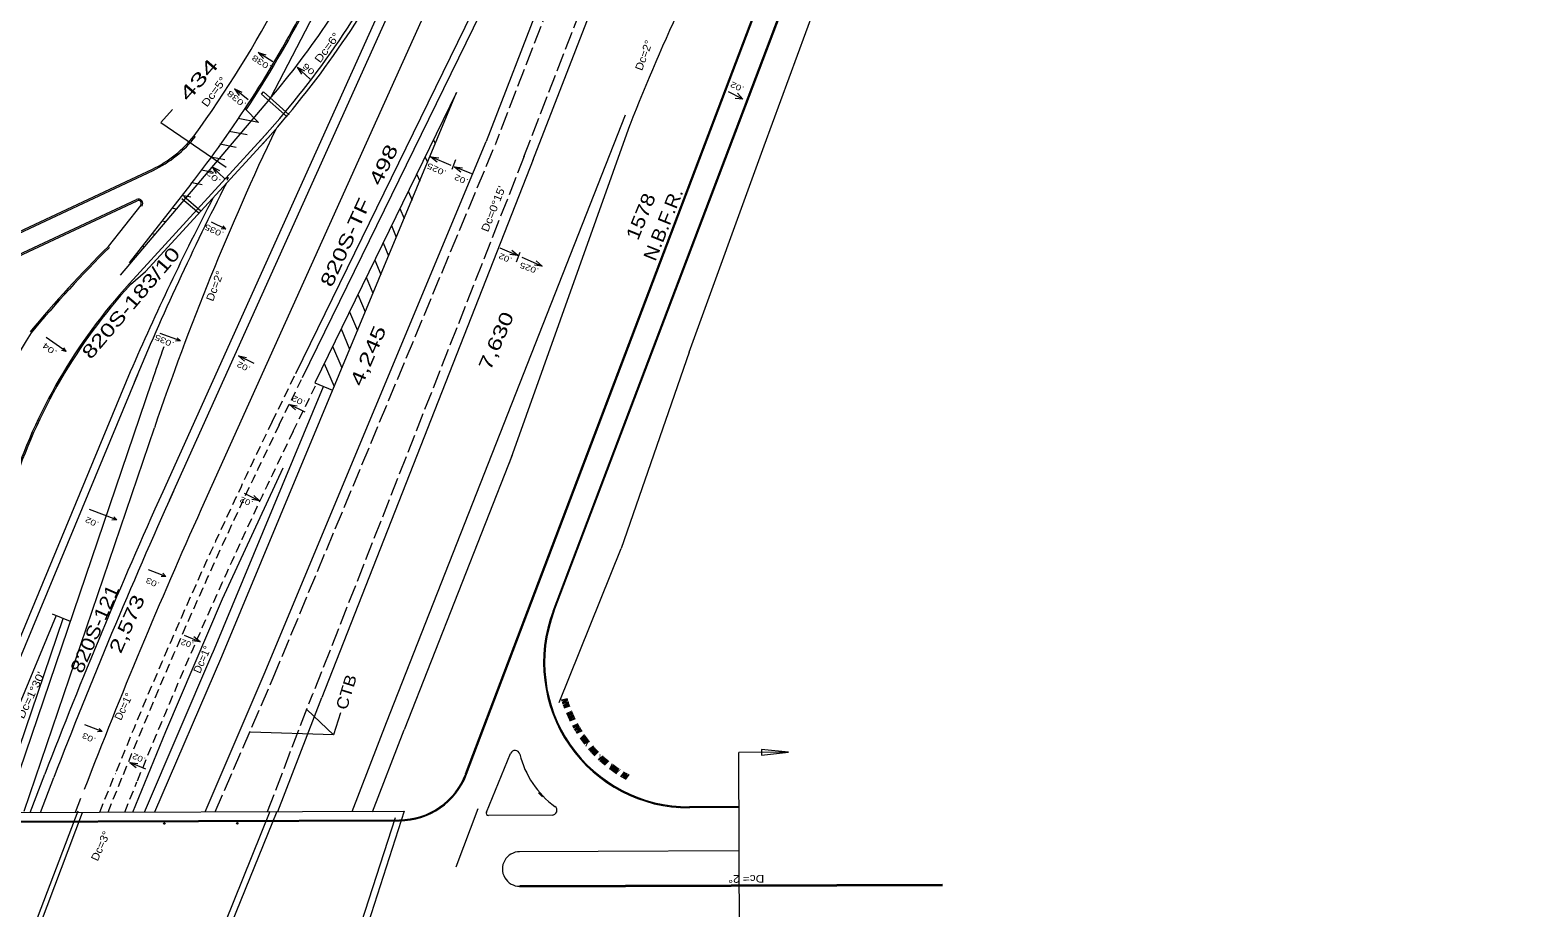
# Model space of a CAD drawing. Extents: x 2354993 to 2372084, y 6966390 to 6990057.
# Drawn here: x 2364884 to 2366452, y 6980481 to 6981393 of the extents above; entities that cross this region are included whole.
import ezdxf

# ---------------------------------------------------------------- set-up
doc = ezdxf.new("R2010")
doc.units = 0
doc.header["$LTSCALE"] = 3.2
doc.header["$PDMODE"] = 32
doc.header["$PDSIZE"] = 1.6
doc.linetypes.add('LONG_DASHED', pattern=[7.5, 6, -1.5])
doc.linetypes.add('MEDIUM_DASHED', pattern=[4.5, 3, -1.5])
for name, color, linetype, lineweight in [('1', 7, 'Continuous', 35), ('11', 7, 'Continuous', 13), ('12', 7, 'Continuous', 13), ('13', 7, 'Continuous', 13), ('15', 7, 'Continuous', 13), ('17', 7, 'Continuous', 13), ('19', 7, 'Continuous', 13), ('25', 7, 'Continuous', 13), ('4', 7, 'Continuous', 13), ('5', 7, 'Continuous', 13), ('7', 7, 'Continuous', 13), ('9', 7, 'Continuous', 13)]:
    doc.layers.add(name, color=color, linetype=linetype, lineweight=lineweight)

msp = doc.modelspace()

# ---------------------------------------------------------------- linework, layer by layer
at = {"layer": '1'}
msp.add_line((2365393.484, 6980503.184), (2365832.993, 6980504.618), dxfattribs=at)
at = {"layer": '11'}
for q in [(2365610.405, 6981329.056), (2365619.803, 6981327.948), (2365617.401, 6981322.432)]:
    msp.add_line((2365625.59, 6981321.562), q, dxfattribs=at)
msp.add_lwpolyline([(2365417.107, 6980596.157), (2365413.024, 6980600.471), (2365417.107, 6980596.157)], dxfattribs=at)
at = {"layer": '12'}
for p, q in [((2365125.058, 6981326.907), (2365127.058, 6981329.143)), ((2365125.058, 6981326.907), (2365151.575, 6981303.182)), ((2365127.058, 6981329.143), (2365153.598, 6981305.398)), ((2365059.879, 6981202.904), (2365042.143, 6981217.955)), ((2365061.904, 6981205.119), (2365044.105, 6981220.225)), ((2364889.34, 6980463.063), (2364934.323, 6980581.712)), ((2364895.069, 6980464.071), (2364938.998, 6980579.939)), ((2365133.691, 6980580.838), (2365086.673, 6980464.691)), ((2365140.767, 6980580.861), (2365093.748, 6980464.714)), ((2365263.831, 6980574.448), (2365228.608, 6980465.09)), ((2365273.39, 6980581.292), (2365235.902, 6980464.902))]:
    msp.add_line(p, q, dxfattribs=at)
at = {"layer": '13'}
msp.add_lwpolyline([(2365032.472, 6981310.938), (2365020.251, 6981297.462), (2365088.313, 6981250.891)], dxfattribs=at)
at = {"layer": '15'}
for p in [(2365672.832, 6980642.571), (2365622.178, 6980409.332)]:
    msp.add_line(p, (2365621.422, 6980642.404), dxfattribs=at)
msp.add_lwpolyline([(2365672.832, 6980642.571), (2365644.822, 6980645.48), (2365644.842, 6980639.481)], close=True, dxfattribs=at)
at = {"layer": '19'}
for p, q in [((2365121.444, 6981370.154), (2365126.945, 6981363.93)), ((2365121.444, 6981370.154), (2365129.403, 6981367.761)), ((2365136.609, 6981360.443), (2365121.444, 6981370.154)), ((2365162.209, 6981354.708), (2365166.546, 6981347.624)), ((2365162.209, 6981354.708), (2365169.632, 6981350.969)), ((2365175.457, 6981342.512), (2365162.209, 6981354.708)), ((2365097.007, 6981332.243), (2365101.772, 6981325.439)), ((2365097.007, 6981332.243), (2365104.646, 6981328.969)), ((2365110.982, 6981320.886), (2365097.007, 6981332.243)), ((2365301.151, 6981261.455), (2365307.649, 6981256.281)), ((2365301.151, 6981261.455), (2365309.405, 6981260.48)), ((2365322.242, 6981252.661), (2365301.151, 6981261.455)), ((2365073.768, 6981251.325), (2365077.965, 6981244.157)), ((2365073.768, 6981251.325), (2365081.116, 6981247.442)), ((2365086.775, 6981238.871), (2365073.768, 6981251.325)), ((2365326.815, 6981258.432), (2365322.862, 6981248.333)), ((2365325.805, 6981251.294), (2365332.303, 6981246.12)), ((2365325.805, 6981251.294), (2365334.058, 6981250.319)), ((2365343.62, 6981243.866), (2365325.805, 6981251.294)), ((2365101.134, 6981054.568), (2365107.331, 6981049.037)), ((2365101.134, 6981054.568), (2365109.32, 6981053.131)), ((2365117.339, 6981046.715), (2365101.134, 6981054.568)), ((2365153.99, 6981004.019), (2365160.187, 6980998.488)), ((2365153.99, 6981004.019), (2365162.176, 6981002.582)), ((2365170.195, 6980996.166), (2365153.99, 6981004.019)), ((2365122.978, 6980903.802), (2365114.831, 6980905.444)), ((2365061.108, 6980757.5), (2365052.846, 6980758.396)), ((2364988.033, 6980631.938), (2364996.28, 6980630.907))]:
    msp.add_line(p, q, dxfattribs=at)
for points in [[(2365106.977, 6980912.062), (2365122.978, 6980903.802), (2365116.923, 6980909.487)], [(2365044.423, 6980764.273), (2365061.108, 6980757.5), (2365054.562, 6980762.612)], [(2365004.606, 6980624.894), (2364988.033, 6980631.938), (2364994.495, 6980626.72)]]:
    msp.add_lwpolyline(points, dxfattribs=at)
at = {"layer": '25'}
for p, q in [((2365683.228, 6982117.169), (2365358.55, 6981277.634)), ((2365407.217, 6981257.934), (2365731.885, 6982097.447)), ((2365029.335, 6980904.779), (2365448.587, 6981835.455)), ((2365382.326, 6981472.187), (2365167.295, 6981031.876)), ((2365083.539, 6980742.181), (2365327.767, 6981328.565)), ((2365327.767, 6981328.565), (2365180.29, 6981026.581)), ((2365132.253, 6981287.979), (2364987.673, 6981129.869)), ((2365127.849, 6980723.726), (2365358.55, 6981277.634)), ((2365407.521, 6981258.707), (2365187.636, 6980699.526)), ((2365051.37, 6981233.14), (2364987.232, 6981151.398)), ((2365090.897, 6981239.272), (2365087.397, 6981239.272)), ((2365089.147, 6981241.022), (2365089.147, 6981237.522)), ((2364999.333, 6981211.369), (2364965.597, 6981168.373)), ((2365087.853, 6981186.245), (2365072.864, 6981193.81)), ((2365087.853, 6981186.245), (2365082.859, 6981186.653)), ((2365087.853, 6981186.245), (2365084.997, 6981189.742)), ((2365372.833, 6981167.08), (2365391.564, 6981159.03)), ((2365391.564, 6981159.03), (2365383.322, 6981160.095)), ((2365391.564, 6981159.03), (2365385.123, 6981164.274)), ((2365390.132, 6981152.333), (2365393.897, 6981162.504)), ((2365395.606, 6981157.245), (2365416.941, 6981148.076)), ((2365416.941, 6981148.076), (2365410.499, 6981153.32)), ((2365416.941, 6981148.076), (2365408.698, 6981149.141)), ((2364987.673, 6981129.869), (2364988.78, 6981128.857)), ((2364921.894, 6981059.311), (2364901.059, 6981073.892)), ((2365040.609, 6981070.164), (2365019.682, 6981078.089)), ((2365040.609, 6981070.164), (2365037.401, 6981073.341)), ((2364921.894, 6981059.311), (2364917.006, 6981060.413)), ((2364921.894, 6981059.311), (2364919.555, 6981063.172)), ((2365040.609, 6981070.164), (2365035.6, 6981070.044)), ((2364995.931, 6981035.023), (2364806.866, 6980579.777)), ((2364861.207, 6980586.955), (2365010.841, 6981027.825)), ((2365180.29, 6981026.581), (2365198.806, 6981019.036)), ((2364974.461, 6980884.074), (2364946.096, 6980894.816)), ((2364974.461, 6980884.074), (2364971.253, 6980887.251)), ((2364974.461, 6980884.074), (2364969.452, 6980883.954)), ((2365025.65, 6980825.433), (2365007.554, 6980832.286)), ((2365025.65, 6980825.433), (2365020.641, 6980825.313)), ((2365025.65, 6980825.433), (2365022.442, 6980828.61)), ((2364926.249, 6980778.591), (2364907.779, 6980786.263)), ((2365014.176, 6980580.45), (2365083.539, 6980742.181)), ((2365066.472, 6980580.62), (2365127.849, 6980723.726)), ((2365141.795, 6980580.864), (2365187.636, 6980699.526)), ((2365199.84, 6980660.583), (2365172.164, 6980687.071)), ((2365206.926, 6980683.485), (2365199.84, 6980660.583)), ((2364959.397, 6980664.047), (2364941.301, 6980670.9)), ((2364959.397, 6980664.047), (2364956.189, 6980667.224)), ((2364959.397, 6980664.047), (2364954.388, 6980663.927)), ((2365199.84, 6980660.583), (2365113.429, 6980663.421)), ((2364766.428, 6980569.647), (2365268.294, 6980571.275))]:
    msp.add_line(p, q, dxfattribs=at)
at = {"layer": '25', "linetype": 'LONG_DASHED'}
for p, q in [((2365692.555, 6982113.562), (2365367.877, 6981274.027)), ((2365397.89, 6981261.541), (2365722.558, 6982101.054)), ((2365137.08, 6980719.881), (2365367.781, 6981273.789)), ((2365398.215, 6981262.367), (2365178.33, 6980703.186)), ((2365076.877, 6980580.654), (2365137.08, 6980719.881)), ((2365131.062, 6980580.83), (2365178.308, 6980703.13))]:
    msp.add_line(p, q, dxfattribs=at)
at = {"layer": '25', "linetype": 'MEDIUM_DASHED'}
for p, q in [((2365143.357, 6980982.86), (2365166.408, 6981030.061)), ((2364965.372, 6980580.292), (2364980.472, 6980617.592))]:
    msp.add_line(p, q, dxfattribs=at)
at = {"layer": '25'}
for centre, radius, start, end in [((2364406.014, 6981928.856), 968.58, 317.77096, 332.59746), ((2364129.385, 6981956.555), 1144.416, 323.97105, 332.59766), ((2364129.386, 6981956.557), 1171.916, 321.88117, 332.59727), ((2364129.386, 6981956.557), 1173.416, 326.58947, 332.59727), ((2367638.31, 6979928.259), 2864.789, 152.87957, 157.44674), ((2364996.973, 6981213.221), 4.5, 321.88153, 115.06276), ((2364996.973, 6981213.221), 3, 321.88153, 115.06276), ((2365859.616, 6980268.609), 1268.414, 134.80816, 140.24643), ((2365859.616, 6980268.609), 1266.914, 134.80816, 140.24643), ((2365412.01, 6980741.844), 575, 137.55934, 162.17959), ((2365412.01, 6980741.844), 573.5, 137.55934, 162.17959), ((2365412.01, 6980741.844), 625, 147.37736, 162.17959), ((2367728.605, 6980105.384), 2870.041, 160.48763, 161.25221)]:
    msp.add_arc(centre, radius, start, end, dxfattribs=at)
at = {"layer": '25', "linetype": 'MEDIUM_DASHED'}
msp.add_arc((2370304.373, 6978462.422), 5743.578, 153.97093, 157.96139, dxfattribs=at)
at = {"layer": '4'}
for p, q in [((2365645.882, 6982190.639), (2365062.309, 6980895.203)), ((2365290.106, 6981508.007), (2365022.191, 6980913.275)), ((2365364.685, 6981454.295), (2365160.333, 6981035.852)), ((2365133.154, 6981321.567), (2364977.995, 6981138.719)), ((2365135.254, 6981285.334), (2365004.504, 6981142.347)), ((2364988.78, 6981128.857), (2365004.504, 6981142.347)), ((2364988.543, 6981038.091), (2364798.192, 6980579.749)), ((2364878.249, 6980581.158), (2365013.559, 6980979.825)), ((2365136.169, 6980986.37), (2365136.168, 6980986.371)), ((2364911.473, 6980784.729), (2364826.382, 6980579.841)), ((2364853.631, 6980589.527), (2364918.845, 6980781.667)), ((2364884.273, 6980580.029), (2364899.617, 6980619.817)), ((2364973.057, 6980620.594), (2364973.056, 6980620.594)), ((2364931.49, 6980580.182), (2364937.08, 6980594.676))]:
    msp.add_line(p, q, dxfattribs=at)
for centre, radius, start, end in [((2364406.014, 6981928.856), 972.58, 317.77096, 332.59746), ((2364530.202, 6981842.504), 796.823, 319.17372, 334.00023), ((2367722.565, 6980060.369), 2860.789, 154.53387, 161.25242), ((2367561.728, 6979924.188), 2803.937, 152.49424, 156.59276), ((2370277.17, 6978545.992), 5763.578, 155.74921, 158.91113), ((2370277.17, 6978545.992), 5719.578, 155.74921, 158.91113), ((2370277.171, 6978545.993), 5719.578, 155.74921, 158.91113)]:
    msp.add_arc(centre, radius, start, end, dxfattribs=at)
at = {"layer": '5'}
for p, q in [((2365337.246, 6980620.046), (2365860.175, 6981999.596)), ((2365338.182, 6980619.691), (2365861.11, 6981999.242)), ((2365428.134, 6980789.285), (2365883.552, 6981990.735)), ((2365429.069, 6980788.933), (2365884.487, 6981990.381)), ((2365134.648, 6981323.301), (2365354.45, 6981747.299)), ((2365107.814, 6981311.509), (2365121.964, 6981297.375)), ((2365121.964, 6981297.375), (2365100.748, 6981301.544)), ((2365503.014, 6981304.804), (2365254.641, 6980673.177)), ((2365507.902, 6981294.902), (2365382.614, 6980943.196)), ((2365110.205, 6981284.399), (2365091.234, 6981288.127)), ((2365303.932, 6981279.375), (2365305.515, 6981275.613)), ((2365086.673, 6981258.449), (2365072.205, 6981261.292)), ((2365098.445, 6981271.423), (2365081.719, 6981274.71)), ((2365295.272, 6981261.277), (2365297.508, 6981255.961)), ((2364462.463, 6980991.963), (2365011.662, 6981248.793)), ((2364463.098, 6980990.605), (2365012.297, 6981247.435)), ((2365074.898, 6981245.476), (2365062.691, 6981247.875)), ((2365063.123, 6981232.503), (2365052.409, 6981234.609)), ((2365286.611, 6981243.18), (2365289.499, 6981236.312)), ((2364471.57, 6980972.489), (2364995.066, 6981217.297)), ((2364472.205, 6980971.129), (2364995.702, 6981215.939)), ((2365051.348, 6981219.53), (2365042.064, 6981221.355)), ((2365277.617, 6981225.874), (2365281.491, 6981216.66)), ((2365036.134, 6981207.233), (2365031.719, 6981208.101)), ((2365268.873, 6981207.97), (2365273.228, 6981197.62)), ((2365025.016, 6981194.131), (2365021.33, 6981194.855)), ((2365260.131, 6981190.069), (2365265.132, 6981178.18)), ((2365002.78, 6981167.927), (2365000.546, 6981168.366)), ((2365013.898, 6981181.029), (2365010.938, 6981181.61)), ((2365251.388, 6981172.166), (2365257.035, 6981158.74)), ((2364991.662, 6981154.825), (2364990.153, 6981155.121)), ((2365242.645, 6981154.264), (2365248.938, 6981139.3)), ((2365233.902, 6981136.361), (2365240.842, 6981119.86)), ((2365225.159, 6981118.458), (2365232.745, 6981100.421)), ((2365216.417, 6981100.556), (2365224.649, 6981080.981)), ((2365207.673, 6981082.652), (2365216.553, 6981061.542)), ((2365198.93, 6981064.75), (2365208.456, 6981042.102)), ((2365569.779, 6981058.596), (2365498.857, 6980854.505)), ((2365190.187, 6981046.847), (2365200.36, 6981022.664)), ((2365074.308, 6980746.026), (2365189.582, 6981022.795)), ((2365385.532, 6980951.387), (2365273.254, 6980665.858)), ((2365084.495, 6980802.006), (2365147.321, 6980938.24)), ((2365434.56, 6980694.195), (2365498.857, 6980854.505)), ((2365025.318, 6980664.238), (2365084.495, 6980802.006)), ((2365290.982, 6980765.594), (2365254.641, 6980673.177)), ((2365003.28, 6980580.415), (2365074.349, 6980746.123)), ((2365219.078, 6980581.116), (2365254.798, 6980673.58)), ((2365240.345, 6980580.67), (2365273.254, 6980665.858)), ((2364991.134, 6980580.375), (2365025.318, 6980664.238)), ((2365358.829, 6980580.308), (2365383.947, 6980641.322)), ((2364895.004, 6980580.063), (2364908.948, 6980616.22)), ((2364766.425, 6980570.647), (2365268.291, 6980572.275)), ((2364776.569, 6980579.679), (2365273.39, 6980581.292)), ((2365327.373, 6980523.465), (2365350.309, 6980583.974)), ((2365427.136, 6980577.093), (2365361.15, 6980576.856)), ((2365621.609, 6980584.953), (2365558.252, 6980584.725)), ((2365621.605, 6980585.953), (2365569.872, 6980585.766)), ((2365620.804, 6980540.003), (2365475.062, 6980539.477)), ((2365475.062, 6980539.477), (2365393.369, 6980539.184)), ((2365393.484, 6980503.184), (2365620.901, 6980503.926))]:
    msp.add_line(p, q, dxfattribs=at)
at = {"layer": '5', "linetype": 'MEDIUM_DASHED'}
for p, q in [((2365136.168, 6980986.371), (2365160.333, 6981035.852)), ((2365157.922, 6980976.222), (2365182.087, 6981025.703)), ((2364956.731, 6980580.264), (2364973.057, 6980620.594)), ((2364982.689, 6980580.348), (2364995.491, 6980611.973))]:
    msp.add_line(p, q, dxfattribs=at)
at = {"layer": '5'}
msp.add_lwpolyline([(2365569.779, 6981058.596), (2365647.705, 6981272.931), (2365768.875, 6981603.207)], dxfattribs=at)
for centre, radius, start, end in [((2368160.706, 6980234.736), 2856.789, 155.3684, 158.22353), ((2364957.343, 6981360.523), 124.234, 295.92761, 321.67524), ((2364957.108, 6981361.383), 126.61, 295.84286, 321.59049), ((2370277.171, 6978545.993), 5753.578, 155.69737, 158.91113), ((2365569.331, 6980735.765), 151, 159.24044, 270.20679), ((2365569.331, 6980735.765), 150, 159.24044, 270.20679), ((2365388.571, 6980639.418), 5, 14.12521, 157.62419), ((2365487.487, 6980664.31), 97, 194.12521, 233.71172), ((2365268.051, 6980646.275), 74, 270.18589, 339.24044), ((2365268.051, 6980646.275), 75, 270.18589, 339.24044), ((2365361.142, 6980579.356), 2.5, 157.62237, 270.20608), ((2365427.118, 6980582.093), 5, 270.20614, 53.71172), ((2365393.427, 6980521.184), 18, 90.18227, 270.18651)]:
    msp.add_arc(centre, radius, start, end, dxfattribs=at)
at = {"layer": '5', "linetype": 'MEDIUM_DASHED'}
for centre, radius in [((2370304.373, 6978462.422), 5751.578), ((2370304.561, 6978462.806), 5727.578)]:
    msp.add_arc(centre, radius, 153.97093, 157.96139, dxfattribs=at)
at = {"layer": '5', "linetype": 'MEDIUM_DASHED', "lineweight": 90}
msp.add_arc((2365569.331, 6980735.765), 135, 196.19769, 241.83611, dxfattribs=at)
at = {"layer": '9'}
msp.add_arc((2360722.521, 6984327.136), 5729.573, 359.50797, 359.50797, dxfattribs=at)
for p in [(2365023.897, 6980568.469), (2365099.889, 6980568.715)]:
    msp.add_point(p, dxfattribs=at)

# ---------------------------------------------------------------- texts
at = {"layer": '13'}
for s, height, rotation, width, p in [('434', 14, 49.17, 1.6, (2365048.557, 6981318.421)), ('498', 14, 64.378, 1.4, (2365248.614, 6981230.708)), ('820S-TF', 14, 65.205, 1.35, (2365198.021, 6981125.166)), ('N.B.F.R.', 14, 68.262, 1.1, (2365534.533, 6981152.233)), ('820S-183/10', 14, 49.529, 1.35, (2364947.51, 6981050.143)), ('7,630', 14, 66.706, 1.35, (2365362.921, 6981038.511)), ('4,245', 14, 66.706, 1.4, (2365229.223, 6981021.971)), ('820S-121', 14, 66.256, 1.2, (2364938.424, 6980723.45)), ('2,573', 14, 66.238, 1.35, (2364978.693, 6980744.315)), ('CTB', 12, 72.807, 1.15, (2365213.414, 6980685.71))]:
    msp.add_text(s, height=height, rotation=rotation, dxfattribs=dict(at, width=width)).set_placement(p)
at = {"layer": '17'}
for s, rotation, width, p in [('Dc=6°', 53.429, 1.2, (2365185.862, 6981358.543)), ('Dc=5°', 53.429, 1.2, (2365068.271, 6981312.687)), ("Dc=0°15'", 68.332, 1.15, (2365360.465, 6981182.811)), ('Dc=2°', 69.418, 1.1, (2365074.528, 6981110.713)), ("Dc=1°30'", 64.778, 1.2, (2364877.588, 6980676.573))]:
    msp.add_text(s, height=8, rotation=rotation, dxfattribs=dict(at, width=width)).set_placement(p)
for rotation, p in [(66.444, (2365061.035, 6980723.859)), (64.778, (2364978.891, 6980675.019))]:
    msp.add_text('Dc=1°', height=8, rotation=rotation, dxfattribs=at).set_placement(p)
at = {"layer": '19'}
for s, height, rotation, width, p in [('Dc=2°', 8, 69.681, 1.1, (2365520.616, 6981350.556)), ('.038', 6, 147.408, 1.4, (2365135.804, 6981356.248)), ('.06', 6, 137.408, 1.5, (2365183.353, 6981348.337)), ('.02', 6, 154.917, 1.3, (2365627.397, 6981333.983)), ('.038', 6, 140.942, 1.45, (2365109.71, 6981316.808)), ('.02', 6, 136.287, 1.55, (2365083.184, 6981236.959)), ('.025', 5.999, 155.55, 1.35, (2365317.856, 6981246.809)), ('.02', 6, 155.855, 1.3, (2365340.46, 6981237.835)), ('1578', 14, 67.763, 1.2, (2365516.336, 6981173.829)), ('.035', 5.999, 154.64, 1.35, (2365086.525, 6981183.021)), ('.035', 5.999, 154.83, 1.35, (2365034.729, 6981068.481)), ('.04', 5.999, 143.171, 1.45, (2364912.905, 6981059.251)), ('.02', 6, 154.187, 1.3, (2365114.207, 6981042.942)), ('.02', 6, 154.187, 1.3, (2365171.224, 6981007.688)), ('.02', 6, 157.881, 1.25, (2365116.84, 6980903.297)), ('.02', 5.999, 154.83, 1.3, (2364956.496, 6980881.547)), ('.03', 5.999, 154.83, 1.3, (2365019.593, 6980818.459)), ('.02', 6, 163.09, 1.2, (2365055.041, 6980756.44)), ('.03', 5.999, 154.83, 1.3, (2364953.34, 6980657.073)), ('.02', 6, 157.016, 1.25, (2365005.065, 6980636.453))]:
    msp.add_text(s, height=height, rotation=rotation, dxfattribs=dict(at, width=width)).set_placement(p)
at = {"layer": '25'}
for s, height, rotation, width, p in [('.02', 5.999, 156.311, 1.25, (2365386.068, 6981156.254)), ('.025', 6, 159.683, 1.3, (2365413.904, 6981145.152))]:
    msp.add_text(s, height=height, rotation=rotation, dxfattribs=dict(at, width=width)).set_placement(p)
at = {"layer": '7'}
for s, rotation, width, p in [('Dc=3°', 65.904, 1.1, (2364954.6, 6980528.689)), ('Dc= 2° ', 180.548, 1.15, (2365647.622, 6980515.096))]:
    msp.add_text(s, height=7.999, rotation=rotation, dxfattribs=dict(at, width=width)).set_placement(p)

doc.saveas('drawing.dxf')
